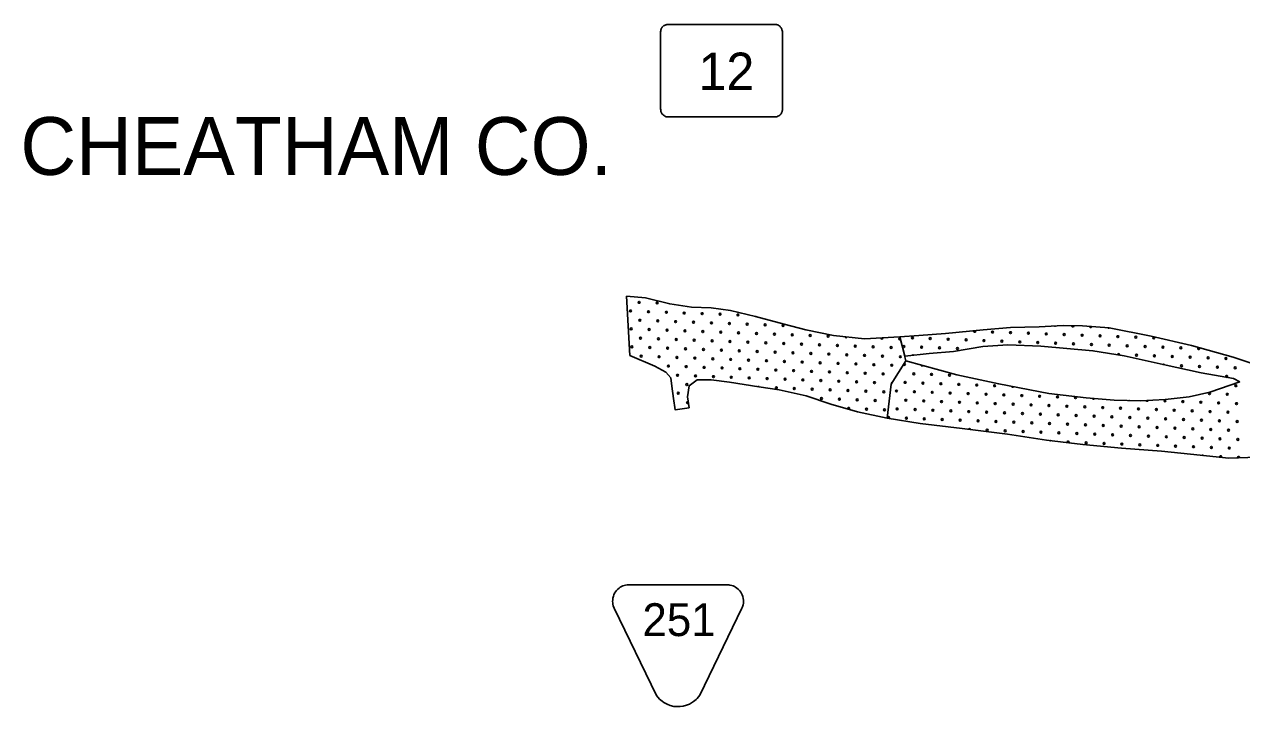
# Model space of a CAD drawing. Extents: x 1612280 to 1883141, y 560852 to 780851.
# Drawn here: x 1668531 to 1682241, y 680870 to 688550 of the extents above; entities that cross this region are included whole.
import ezdxf

# ---------------------------------------------------------------- set-up
doc = ezdxf.new("R2010")
doc.units = 0
for name, color, linetype in [('DESIGN - ROW - Easement Linework and Patterning', 7, 'Continuous'), ('DESIGN - ROW - Slope Lines', 7, 'Continuous'), ('DESIGN - SCRATCH - User 1', 7, 'Continuous'), ('DESIGN - TRAFFIC CONTROL PERMANENT - Pavement Marking Text', 7, 'Continuous'), ('SURVEY - DRAINAGE - Natural Features', 7, 'Continuous')]:
    doc.layers.add(name, color=color, linetype=linetype)

msp = doc.modelspace()

# ---------------------------------------------------------------- linework, layer by layer
at = {"layer": 'DESIGN - ROW - Easement Linework and Patterning'}
for points in [[(1675649, 680996), (1675174, 681977), (1675164, 682004), (1675159, 682022), (1675157, 682039), (1675156, 682055), (1675157, 682073), (1675159, 682089), (1675165, 682113), (1675171, 682130), (1675179, 682146), (1675189, 682162), (1675199, 682176), (1675215, 682192), (1675229, 682204), (1675242, 682213), (1675255, 682221), (1675271, 682228), (1675287, 682234), (1675300, 682237), (1675321, 682241), (1675341, 682242)], [(1675649, 680996), (1675174, 681977), (1675164, 682004), (1675159, 682022), (1675157, 682039), (1675156, 682055), (1675157, 682073), (1675159, 682089), (1675165, 682113), (1675171, 682130), (1675179, 682146), (1675189, 682162), (1675199, 682176), (1675215, 682192), (1675229, 682204), (1675242, 682213), (1675255, 682221), (1675271, 682228), (1675287, 682234), (1675300, 682237), (1675321, 682241), (1675341, 682242)], [(1676611, 681977), (1676618, 681994), (1676626, 682017), (1676629, 682034), (1676630, 682054), (1676630, 682070), (1676627, 682088), (1676622, 682110), (1676616, 682128), (1676609, 682143), (1676600, 682158), (1676589, 682174), (1676576, 682188), (1676557, 682204), (1676542, 682214), (1676528, 682222), (1676514, 682229), (1676498, 682234), (1676478, 682239), (1676464, 682241), (1676445, 682242), (1675341, 682242)], [(1676611, 681977), (1676618, 681994), (1676626, 682017), (1676629, 682034), (1676630, 682054), (1676630, 682070), (1676627, 682088), (1676622, 682110), (1676616, 682128), (1676609, 682143), (1676600, 682158), (1676589, 682174), (1676576, 682188), (1676557, 682204), (1676542, 682214), (1676528, 682222), (1676514, 682229), (1676498, 682234), (1676478, 682239), (1676464, 682241), (1676445, 682242), (1675341, 682242)], [(1676611, 681977), (1676138, 680999), (1676123, 680979), (1676109, 680962), (1676096, 680949), (1676067, 680926), (1676045, 680912), (1676021, 680899), (1675988, 680885), (1675951, 680875), (1675919, 680871), (1675884, 680870), (1675847, 680873), (1675806, 680882), (1675770, 680896), (1675735, 680915), (1675713, 680930), (1675684, 680955), (1675649, 680996)], [(1676611, 681977), (1676138, 680999), (1676123, 680979), (1676109, 680962), (1676096, 680949), (1676067, 680926), (1676045, 680912), (1676021, 680899), (1675988, 680885), (1675951, 680875), (1675919, 680871), (1675884, 680870), (1675847, 680873), (1675806, 680882), (1675770, 680896), (1675735, 680915), (1675713, 680930), (1675684, 680955), (1675649, 680996)]]:
    msp.add_lwpolyline(points, dxfattribs=at)
at = {"layer": 'DESIGN - ROW - Slope Lines'}
msp.add_line((1675696, 688449), (1675696, 687617), dxfattribs=at)
msp.add_line((1675696, 688449), (1675696, 687617), dxfattribs=at)
for points in [[(1677069, 688439), (1677069, 688446), (1677069, 688454), (1677068, 688469), (1677066, 688480), (1677064, 688490), (1677062, 688496), (1677059, 688503), (1677055, 688510), (1677049, 688518), (1677045, 688523), (1677039, 688529), (1677034, 688533), (1677028, 688537), (1677023, 688540), (1677014, 688544), (1677008, 688546), (1677001, 688548), (1676992, 688549), (1676984, 688550), (1676975, 688550), (1676963, 688550), (1676953, 688550), (1675796, 688550), (1675787, 688550), (1675776, 688550), (1675767, 688549), (1675758, 688547), (1675754, 688546), (1675747, 688543), (1675740, 688539), (1675735, 688536), (1675726, 688529), (1675720, 688523), (1675715, 688517), (1675711, 688512), (1675705, 688503), (1675702, 688495), (1675700, 688490), (1675699, 688486), (1675699, 688483), (1675698, 688476), (1675697, 688466), (1675696, 688459), (1675696, 688452), (1675696, 688434)], [(1677069, 688439), (1677069, 688446), (1677069, 688454), (1677068, 688469), (1677066, 688480), (1677064, 688490), (1677062, 688496), (1677059, 688503), (1677055, 688510), (1677049, 688518), (1677045, 688523), (1677039, 688529), (1677034, 688533), (1677028, 688537), (1677023, 688540), (1677014, 688544), (1677008, 688546), (1677001, 688548), (1676992, 688549), (1676984, 688550), (1676975, 688550), (1676963, 688550), (1676953, 688550), (1675796, 688550), (1675787, 688550), (1675776, 688550), (1675767, 688549), (1675758, 688547), (1675754, 688546), (1675747, 688543), (1675740, 688539), (1675735, 688536), (1675726, 688529), (1675720, 688523), (1675715, 688517), (1675711, 688512), (1675705, 688503), (1675702, 688495), (1675700, 688490), (1675699, 688486), (1675699, 688483), (1675698, 688476), (1675697, 688466), (1675696, 688459), (1675696, 688452), (1675696, 688434)], [(1676959, 687508), (1676980, 687508), (1676997, 687509), (1677007, 687511), (1677019, 687516), (1677030, 687522), (1677039, 687529), (1677047, 687537), (1677054, 687545), (1677060, 687555), (1677063, 687563), (1677066, 687570), (1677067, 687577), (1677068, 687585), (1677068, 687595), (1677069, 687619), (1677069, 688439)], [(1676959, 687508), (1676980, 687508), (1676997, 687509), (1677007, 687511), (1677019, 687516), (1677030, 687522), (1677039, 687529), (1677047, 687537), (1677054, 687545), (1677060, 687555), (1677063, 687563), (1677066, 687570), (1677067, 687577), (1677068, 687585), (1677068, 687595), (1677069, 687619), (1677069, 688439)], [(1675696, 687617), (1675696, 687608), (1675697, 687598), (1675698, 687589), (1675699, 687579), (1675700, 687570), (1675703, 687563), (1675706, 687555), (1675711, 687548), (1675716, 687541), (1675722, 687534), (1675729, 687528), (1675736, 687523), (1675744, 687518), (1675753, 687514), (1675761, 687511), (1675769, 687510), (1675784, 687509), (1675802, 687508), (1676959, 687508)], [(1675696, 687617), (1675696, 687608), (1675697, 687598), (1675698, 687589), (1675699, 687579), (1675700, 687570), (1675703, 687563), (1675706, 687555), (1675711, 687548), (1675716, 687541), (1675722, 687534), (1675729, 687528), (1675736, 687523), (1675744, 687518), (1675753, 687514), (1675761, 687511), (1675769, 687510), (1675784, 687509), (1675802, 687508), (1676959, 687508)]]:
    msp.add_lwpolyline(points, dxfattribs=at)
at = {"layer": 'DESIGN - SCRATCH - User 1'}
for points in [[(1675351, 684822), (1675313, 685490), (1675526, 685471), (1675799, 685404), (1676045, 685366), (1676267, 685361), (1676483, 685331), (1676765, 685263), (1677089, 685174)], [(1675351, 684822), (1675313, 685490), (1675526, 685471), (1675799, 685404), (1676045, 685366), (1676267, 685361), (1676483, 685331), (1676765, 685263), (1677089, 685174)], [(1677089, 685174), (1677332, 685110), (1677646, 685047), (1677994, 685012), (1678392, 685034)], [(1677089, 685174), (1677332, 685110), (1677646, 685047), (1677994, 685012), (1678392, 685034)], [(1678392, 685034), (1678606, 685048), (1678906, 685069), (1679331, 685112), (1679638, 685137), (1679959, 685144), (1680231, 685162), (1680449, 685155), (1680749, 685133), (1681224, 685040), (1681678, 684934), (1682146, 684805), (1682496, 684687), (1682771, 684562), (1683074, 684444), (1683453, 684301), (1683963, 684130)], [(1678392, 685034), (1678606, 685048), (1678906, 685069), (1679331, 685112), (1679638, 685137), (1679959, 685144), (1680231, 685162), (1680449, 685155), (1680749, 685133), (1681224, 685040), (1681678, 684934), (1682146, 684805), (1682496, 684687), (1682771, 684562), (1683074, 684444), (1683453, 684301), (1683963, 684130)], [(1678392, 685034), (1678460, 684763), (1678292, 684501), (1678248, 684117)], [(1678392, 685034), (1678460, 684763), (1678292, 684501), (1678248, 684117)], [(1682220, 684525), (1682151, 684562), (1681784, 684628), (1681357, 684721), (1680918, 684818), (1680566, 684877), (1679979, 684929), (1679606, 684941), (1679328, 684925), (1678994, 684869), (1678720, 684845), (1678447, 684816), (1678392, 685034)], [(1682220, 684525), (1682151, 684562), (1681784, 684628), (1681357, 684721), (1680918, 684818), (1680566, 684877), (1679979, 684929), (1679606, 684941), (1679328, 684925), (1678994, 684869), (1678720, 684845), (1678447, 684816), (1678392, 685034)], [(1676020, 684232), (1675860, 684211), (1675841, 684337), (1675825, 684476), (1675813, 684571), (1675757, 684635), (1675633, 684703), (1675351, 684822)], [(1676020, 684232), (1675860, 684211), (1675841, 684337), (1675825, 684476), (1675813, 684571), (1675757, 684635), (1675633, 684703), (1675351, 684822)], [(1678249, 684117), (1678292, 684500), (1678460, 684763), (1679034, 684606), (1679505, 684502), (1680070, 684395), (1680491, 684345), (1680805, 684320), (1681102, 684313), (1681380, 684327), (1681652, 684359), (1681884, 684409), (1682220, 684525)], [(1678249, 684117), (1678292, 684500), (1678460, 684763), (1679034, 684606), (1679505, 684502), (1680070, 684395), (1680491, 684345), (1680805, 684320), (1681102, 684313), (1681380, 684327), (1681652, 684359), (1681884, 684409), (1682220, 684525)], [(1678248, 684117), (1677916, 684187), (1677613, 684276), (1677337, 684368), (1677032, 684436), (1676805, 684471), (1676472, 684523), (1676267, 684547), (1676110, 684547), (1676018, 684482), (1675999, 684358), (1676020, 684232)], [(1678248, 684117), (1677916, 684187), (1677613, 684276), (1677337, 684368), (1677032, 684436), (1676805, 684471), (1676472, 684523), (1676267, 684547), (1676110, 684547), (1676018, 684482), (1675999, 684358), (1676020, 684232)], [(1683963, 684130), (1683815, 683648), (1683410, 683665), (1683115, 683648), (1682791, 683648), (1682421, 683677), (1682097, 683665), (1681773, 683700), (1681339, 683746), (1680888, 683781), (1680454, 683821), (1680044, 683868), (1679604, 683937), (1679095, 684001), (1678620, 684059), (1678249, 684117)], [(1683963, 684130), (1683815, 683648), (1683410, 683665), (1683115, 683648), (1682791, 683648), (1682421, 683677), (1682097, 683665), (1681773, 683700), (1681339, 683746), (1680888, 683781), (1680454, 683821), (1680044, 683868), (1679604, 683937), (1679095, 684001), (1678620, 684059), (1678249, 684117)]]:
    msp.add_lwpolyline(points, dxfattribs=at)
for centre in [(1677688, 684936), (1677688, 684936), (1677793, 684831), (1677793, 684831)]:
    msp.add_circle(centre, 10.6, dxfattribs=at)
at = {"layer": 'DESIGN - TRAFFIC CONTROL PERMANENT - Pavement Marking Text'}
for centre in [(1675455, 685421), (1675455, 685421), (1675657, 685414), (1675657, 685414), (1675358, 685324), (1675358, 685324), (1675560, 685316), (1675560, 685316), (1675762, 685309), (1675762, 685309), (1675963, 685301), (1675963, 685301), (1676165, 685294), (1676165, 685294), (1676366, 685287), (1676366, 685287), (1676568, 685279), (1676568, 685279), (1675366, 685122), (1675366, 685122), (1675463, 685219), (1675463, 685219), (1675664, 685212), (1675664, 685212), (1675866, 685204), (1675866, 685204), (1676068, 685197), (1676068, 685197), (1676269, 685189), (1676269, 685189), (1676471, 685182), (1676471, 685182), (1676672, 685175), (1676672, 685175), (1676874, 685167), (1676874, 685167), (1677076, 685160), (1677076, 685160), (1675470, 685018), (1675470, 685018), (1675567, 685115), (1675567, 685115), (1675672, 685010), (1675672, 685010), (1675769, 685107), (1675769, 685107), (1675874, 685003), (1675874, 685003), (1675971, 685100), (1675971, 685100), (1676075, 684995), (1676075, 684995), (1676172, 685092), (1676172, 685092), (1676277, 684988), (1676277, 684988), (1676374, 685085), (1676374, 685085), (1676575, 685077), (1676575, 685077), (1676777, 685070), (1676777, 685070), (1676979, 685063), (1676979, 685063), (1677180, 685055), (1677180, 685055), (1677382, 685048), (1677382, 685048), (1677583, 685040), (1677583, 685040), (1678533, 685020), (1678533, 685020), (1678734, 685013), (1678734, 685013), (1678936, 685005), (1678936, 685005), (1679138, 684998), (1679138, 684998), (1679339, 684990), (1679339, 684990), (1679436, 685087), (1679436, 685087), (1679541, 684983), (1679541, 684983), (1679638, 685080), (1679638, 685080), (1679839, 685073), (1679839, 685073), (1680041, 685065), (1680041, 685065), (1680243, 685058), (1680243, 685058), (1680444, 685050), (1680444, 685050), (1680646, 685043), (1680646, 685043), (1680847, 685035), (1680847, 685035), (1681049, 685028), (1681049, 685028), (1681251, 685020), (1681251, 685020), (1675373, 684921), (1675373, 684921), (1675575, 684913), (1675575, 684913), (1675776, 684906), (1675776, 684906), (1675978, 684898), (1675978, 684898), (1676180, 684891), (1676180, 684891), (1676381, 684883), (1676381, 684883), (1676478, 684980), (1676478, 684980), (1676583, 684876), (1676583, 684876), (1676680, 684973), (1676680, 684973), (1676785, 684868), (1676785, 684868), (1676882, 684965), (1676882, 684965), (1676986, 684861), (1676986, 684861), (1677083, 684958), (1677083, 684958), (1677188, 684853), (1677188, 684853), (1677285, 684951), (1677285, 684951), (1677389, 684846), (1677389, 684846), (1677486, 684943), (1677486, 684943), (1677890, 684928), (1677890, 684928), (1678091, 684921), (1678091, 684921), (1678293, 684913), (1678293, 684913), (1678436, 684923), (1678436, 684923), (1678637, 684916), (1678637, 684916), (1678839, 684908), (1678839, 684908), (1679040, 684901), (1679040, 684901), (1679742, 684975), (1679742, 684975), (1679944, 684968), (1679944, 684968), (1680146, 684961), (1680146, 684961), (1680347, 684953), (1680347, 684953), (1680549, 684946), (1680549, 684946), (1680750, 684938), (1680750, 684938), (1680952, 684931), (1680952, 684931), (1681154, 684923), (1681154, 684923), (1681355, 684916), (1681355, 684916), (1681557, 684908), (1681557, 684908), (1675478, 684816), (1675478, 684816), (1675679, 684809), (1675679, 684809), (1675881, 684801), (1675881, 684801), (1676083, 684794), (1676083, 684794), (1676284, 684786), (1676284, 684786), (1676486, 684779), (1676486, 684779), (1676687, 684771), (1676687, 684771), (1676889, 684764), (1676889, 684764), (1677091, 684756), (1677091, 684756), (1677292, 684749), (1677292, 684749), (1677494, 684741), (1677494, 684741), (1677591, 684839), (1677591, 684839), (1677695, 684734), (1677695, 684734), (1677897, 684727), (1677897, 684727), (1677994, 684824), (1677994, 684824), (1678099, 684719), (1678099, 684719), (1678196, 684816), (1678196, 684816), (1678300, 684712), (1678300, 684712), (1678397, 684809), (1678397, 684809), (1681057, 684826), (1681057, 684826), (1681258, 684819), (1681258, 684819), (1681460, 684811), (1681460, 684811), (1681564, 684707), (1681564, 684707), (1681661, 684804), (1681661, 684804), (1681863, 684796), (1681863, 684796), (1682065, 684789), (1682065, 684789), (1675784, 684704), (1675784, 684704), (1675888, 684600), (1675888, 684600), (1675986, 684697), (1675986, 684697), (1676090, 684592), (1676090, 684592), (1676187, 684689), (1676187, 684689), (1676292, 684585), (1676292, 684585), (1676389, 684682), (1676389, 684682), (1676493, 684577), (1676493, 684577), (1676590, 684674), (1676590, 684674), (1676695, 684570), (1676695, 684570), (1676792, 684667), (1676792, 684667), (1676994, 684659), (1676994, 684659), (1677195, 684652), (1677195, 684652), (1677397, 684644), (1677397, 684644), (1677598, 684637), (1677598, 684637), (1677800, 684629), (1677800, 684629), (1678002, 684622), (1678002, 684622), (1678203, 684615), (1678203, 684615), (1678548, 684617), (1678548, 684617), (1678749, 684610), (1678749, 684610), (1678951, 684602), (1678951, 684602), (1681766, 684699), (1681766, 684699), (1681968, 684692), (1681968, 684692), (1682169, 684684), (1682169, 684684), (1675993, 684495), (1675993, 684495), (1676897, 684562), (1676897, 684562), (1677001, 684458), (1677001, 684458), (1677098, 684555), (1677098, 684555), (1677203, 684450), (1677203, 684450), (1677300, 684547), (1677300, 684547), (1677404, 684443), (1677404, 684443), (1677501, 684540), (1677501, 684540), (1677606, 684435), (1677606, 684435), (1677703, 684532), (1677703, 684532), (1677905, 684525), (1677905, 684525), (1678106, 684517), (1678106, 684517), (1678451, 684520), (1678451, 684520), (1678652, 684512), (1678652, 684512), (1678854, 684505), (1678854, 684505), (1679055, 684498), (1679055, 684498), (1679257, 684490), (1679257, 684490), (1679459, 684483), (1679459, 684483), (1682177, 684483), (1682177, 684483), (1675896, 684398), (1675896, 684398), (1677509, 684338), (1677509, 684338), (1677710, 684331), (1677710, 684331), (1677807, 684428), (1677807, 684428), (1677912, 684323), (1677912, 684323), (1678009, 684420), (1678009, 684420), (1678114, 684316), (1678114, 684316), (1678211, 684413), (1678211, 684413), (1678353, 684423), (1678353, 684423), (1678458, 684318), (1678458, 684318), (1678555, 684415), (1678555, 684415), (1678660, 684311), (1678660, 684311), (1678757, 684408), (1678757, 684408), (1678861, 684303), (1678861, 684303), (1678958, 684400), (1678958, 684400), (1679063, 684296), (1679063, 684296), (1679160, 684393), (1679160, 684393), (1679362, 684386), (1679362, 684386), (1679563, 684378), (1679563, 684378), (1679765, 684371), (1679765, 684371), (1679966, 684363), (1679966, 684363), (1680168, 684356), (1680168, 684356), (1680370, 684348), (1680370, 684348), (1681378, 684311), (1681378, 684311), (1681579, 684303), (1681579, 684303), (1681781, 684296), (1681781, 684296), (1681878, 684393), (1681878, 684393), (1682080, 684386), (1682080, 684386), (1678017, 684219), (1678017, 684219), (1678218, 684211), (1678218, 684211), (1678361, 684221), (1678361, 684221), (1678563, 684214), (1678563, 684214), (1678764, 684206), (1678764, 684206), (1678966, 684199), (1678966, 684199), (1679167, 684191), (1679167, 684191), (1679264, 684288), (1679264, 684288), (1679369, 684184), (1679369, 684184), (1679466, 684281), (1679466, 684281), (1679571, 684176), (1679571, 684176), (1679668, 684274), (1679668, 684274), (1679772, 684169), (1679772, 684169), (1679869, 684266), (1679869, 684266), (1679974, 684162), (1679974, 684162), (1680071, 684259), (1680071, 684259), (1680273, 684251), (1680273, 684251), (1680474, 684244), (1680474, 684244), (1680676, 684236), (1680676, 684236), (1680877, 684229), (1680877, 684229), (1681079, 684221), (1681079, 684221), (1681281, 684214), (1681281, 684214), (1681482, 684206), (1681482, 684206), (1681684, 684199), (1681684, 684199), (1681885, 684191), (1681885, 684191), (1681982, 684288), (1681982, 684288), (1682087, 684184), (1682087, 684184), (1682184, 684281), (1682184, 684281), (1678465, 684117), (1678465, 684117), (1678667, 684109), (1678667, 684109), (1678869, 684102), (1678869, 684102), (1679070, 684094), (1679070, 684094), (1679272, 684087), (1679272, 684087), (1679474, 684079), (1679474, 684079), (1679675, 684072), (1679675, 684072), (1679877, 684064), (1679877, 684064), (1680078, 684057), (1680078, 684057), (1680175, 684154), (1680175, 684154), (1680280, 684050), (1680280, 684050), (1680377, 684147), (1680377, 684147), (1680482, 684042), (1680482, 684042), (1680579, 684139), (1680579, 684139), (1680683, 684035), (1680683, 684035), (1680780, 684132), (1680780, 684132), (1680885, 684027), (1680885, 684027), (1680982, 684124), (1680982, 684124), (1681184, 684117), (1681184, 684117), (1681385, 684109), (1681385, 684109), (1681587, 684102), (1681587, 684102), (1681788, 684094), (1681788, 684094), (1681990, 684087), (1681990, 684087), (1682192, 684079), (1682192, 684079), (1679376, 683982), (1679376, 683982), (1679578, 683975), (1679578, 683975), (1679780, 683967), (1679780, 683967), (1679981, 683960), (1679981, 683960), (1680183, 683952), (1680183, 683952), (1680385, 683945), (1680385, 683945), (1680586, 683938), (1680586, 683938), (1680788, 683930), (1680788, 683930), (1680989, 683923), (1680989, 683923), (1681086, 684020), (1681086, 684020), (1681191, 683915), (1681191, 683915), (1681288, 684012), (1681288, 684012), (1681393, 683908), (1681393, 683908), (1681490, 684005), (1681490, 684005), (1681594, 683900), (1681594, 683900), (1681691, 683997), (1681691, 683997), (1681796, 683893), (1681796, 683893), (1681893, 683990), (1681893, 683990), (1681997, 683885), (1681997, 683885), (1682094, 683982), (1682094, 683982), (1680489, 683840), (1680489, 683840), (1680691, 683833), (1680691, 683833), (1680892, 683826), (1680892, 683826), (1681094, 683818), (1681094, 683818), (1681296, 683811), (1681296, 683811), (1681497, 683803), (1681497, 683803), (1681699, 683796), (1681699, 683796), (1681900, 683788), (1681900, 683788), (1682102, 683781), (1682102, 683781), (1682199, 683878), (1682199, 683878)]:
    msp.add_circle(centre, 10.6, dxfattribs=at)
for centre, start, end in [((1676770, 685272), 229.2469, 280.7971), ((1680138, 685162), 219.99, 327.5432), ((1680340, 685155), 157.3447, 18.8995), ((1680541, 685147), 170.3872, 1.4353), ((1680743, 685140), 209.9465, 319.9122), ((1677785, 685033), 170.6871, 357.7978), ((1678188, 685018), 154.5348, 31.6988), ((1678390, 685010), 58.4963, 329.7326), ((1679235, 685095), 142.2724, 49.2508), ((1681758, 684901), 89.2317, 60.0171), ((1678443, 684722), 186.3525, 108.6011), ((1678540, 684819), 48.9179, 143.3467), ((1680855, 684834), 322.5106, 198.3885), ((1681363, 684714), 21.4312, 133.8408), ((1678645, 684714), 172.4962, 336.8487), ((1682072, 684587), 267.0965, 252.7111), ((1676799, 684465), 30.4541, 131.9649), ((1678308, 684510), 108.7175, 186.1453), ((1679660, 684475), 181.6003, 336.8831), ((1680571, 684341), 186.8702, 344.0292), ((1680974, 684326), 247.8052, 289.4309), ((1681176, 684318), 191.9671, 353.9111), ((1676000, 684293), 40.8534, 338.0142), ((1677815, 684226), 284.7663, 222.3777), ((1678264, 684124), 284.4376, 237.8421), ((1679175, 683990), 358.8206, 166.9203), ((1680086, 683855), 39.3646, 127.7701), ((1680287, 683848), 307.5594, 219.5752), ((1681803, 683691), 25.5004, 142.2602), ((1682005, 683684), 299.9839, 227.7767), ((1682206, 683676), 319.746, 224.3494)]:
    msp.add_arc(centre, 10.6, start, end, dxfattribs=at)

# ---------------------------------------------------------------- texts
at = {"layer": 'DESIGN - ROW - Easement Linework and Patterning'}
msp.add_text('251', height=369.6, rotation=0.0012, dxfattribs=at).set_placement((1675492, 681664))
msp.add_text('251', height=369.6, rotation=0.0012, dxfattribs=at).set_placement((1675492, 681664))
at = {"layer": 'DESIGN - ROW - Slope Lines'}
msp.add_text('12', height=422.4, rotation=0.0011, dxfattribs=at).set_placement((1676124, 687810))
msp.add_text('12', height=422.4, rotation=0.0011, dxfattribs=at).set_placement((1676124, 687810))
at = {"layer": 'SURVEY - DRAINAGE - Natural Features'}
msp.add_text('CHEATHAM CO.', height=649.98, rotation=0, dxfattribs=at).set_placement((1668486, 686856))
msp.add_text('CHEATHAM CO.', height=649.98, rotation=0, dxfattribs=at).set_placement((1668486, 686856))

doc.saveas('drawing.dxf')
